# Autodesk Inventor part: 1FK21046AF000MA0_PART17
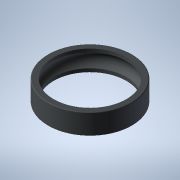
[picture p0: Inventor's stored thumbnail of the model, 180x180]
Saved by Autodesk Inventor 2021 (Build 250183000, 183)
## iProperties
Created: 2025-04
Part Number: 1FK21046AF000MA0_PART17
Material: Generic
Catalog Web Link: www.3dfindit.com
Description: -Servo synchronous motor
Document SubType Name: Modeling
Designer: psAdmin
Mass: 1.64389 g
Surface Area: 26.4305 cm^2
Volume: 1.64389 cm^3
Density: 1 g/cm^3
Appearance: PSOLRGB-212-217-219
Category: PARTsolutions
Title: 1FK21046AF000MA0_PART17
Author: Cadenas PARTsolutions
Comments: Servo synchronous motor
Sending System: PARTsolutions
Preprocessor: ST-DEVELOPER v19.3
PSOL_IDENT_0: {$CADENAS_DATA/23d-libs/siemens_ag/_cat_/1c/1f/1fk21046af000ma0.prj},216 {VTYP=3D},{NB=1FK21046AF000
PSOL_IDENT_1: MA0_PART17},{LINA=1FK21046AF000MA0_PART17},{NN=1FK21046AF000MA0_PART17},{NOPRJ=TRUE},{DATE=19.08.202
PSOL_IDENT_2: 5 14:00:28},{GEOMDATE=30.07.2025 02:02:08},{VERSION=},{LINEID=10},{WBVAR=},{WBNUMERIC=}  {NB=1FK2104
PSOL_IDENT_3: 6AF000MA0_PART17},{LINA=1FK21046AF000MA0_PART17},{KT=DUMMY},{PREVIEW=../../../_pool_/cb/72/p_d211_xx
PSOL_IDENT_4: _00434j.png},{DESCSHORT=SIMOTICS S-1FK2 HD, SINAMICS S210 3AC 400V-480V, 3.2 Nm, 3000 rpm},{DESCLONG=
PSOL_IDENT_5: SIMOTICS S-1FK2 HD servo motor M0=3.2 Nm; PN = 1 kW at nN=3000 rpm (380-480 V); PN = 0.5 kW at nN=15
PSOL_IDENT_6: 00 rpm (200-240 V); degree of protection IP64; cylindrical shaft D19x40mm; absolute encoder 22-bit +
PSOL_IDENT_7: 12-bit multiturn (encoder AM22DQC); with OCC interface; plug size M17, rotatable; SIMOTICS S-1FK2 s
PSOL_IDENT_8: ervomotorfor a wide range of uses in industrial environments. SIMOTICS S‑1FK2 servomotors are compac
PSOL_IDENT_9: t synchronous motors with a high dynamic performance that set themselves apart as a result of their
PSOL_IDENT_10: high power density, degree of protection and overload capability. The motors are available in two va
PSOL_IDENT_11: riants: as High Dynamic variant (highest dynamic performance as a result of the low intrinsic moment
PSOL_IDENT_12: of inertia for applications demanding a high dynamic performance with low moved masses) - and as Co
PSOL_IDENT_13: mpact variant (precise and stable closed-loop control for medium up to large moved masses as a resul
PSOL_IDENT_14: t of a medium intrinsic moment of inertia). SIMOTICSS‑1FK2 servomotors fully exploit their strengths
PSOL_IDENT_15: in a system with the SINAMICSS210 frequency converter and simple connection using the one cable con
PSOL_IDENT_16: nection (OCC). Advantages include the short control and positioning times, fast and precise correcti
PSOL_IDENT_17: on of disturbing quantities as well as stable control with a high dynamic performance. The servo mot
PSOL_IDENT_18: ors can be configured to address a wide range of requirements. For example with and without holding
PSOL_IDENT_19: brake, IP64 or IP65 degree of protection, singleturn or multiturn absolute encoders - to name just a
PSOL_IDENT_20: few. Further, the servomotors are available in different shaft heights extending from 20 to 100. A
PSOL_IDENT_21: shaft sealing ring is available to achieve an IP65 degree of protection and for subsequent mounting
PSOL_IDENT_22: at the motor or as spare part. SIMOTICS - the optimum motor for each and every motion control applic
PSOL_IDENT_23: ation.},{INTNO=195125049666},{SUPPLIERALTNO=1FK2104-6AF00-0MA0},{MANUID=1FK21046AF000MA0},{MANUNAME=
PSOL_IDENT_24: Siemens},{MANUTYPEDESC=Synchronous motor 1FK2-HD 3.2 NM},{AAU732=SIMOTICS},{AAO057=S-1FK2},{AAU734=S
PSOL_IDENT_25: IMOTICS S-1FK2 HD servo motor M0=3.2 Nm; PN = 1 kW at nN=3000 rpm (380-480 V); PN = 0.5 kW at nN=150
PSOL_IDENT_26: 0 rpm (200-240 V); degree of protection IP64; cylindrical shaft D19x40mm; absolute encoder 22-bit +
PSOL_IDENT_27: 12-bit multiturn (encoder AM22DQC); with OCC interface; plug size M17, rotatable;},{AAW338=Synchrono
PSOL_IDENT_28: us motor 1FK2-HD 3.2 NM},{AAO742=SIMOTICS},{AAO663=4042948694374},{NOCUPEROU=1},{PRICEQUANTITY=1},{Q
PSOL_IDENT_29: UANTITYMIN=1},{QUANTITYINT=1},{CTN=85015220},{COO=DE},{AAO676=1FK2104-6AF00-0MA0},{AAO677=Siemens AG
PSOL_IDENT_30: },{ORDERUNIT=C62},{CONTENTUNIT=C62}
NB: 1FK21046AF000MA0_PART17
NT: Servo synchronous motor
NBSYN: $MANUID._PART17
LINA: 1FK21046AF000MA0_PART17
CATALOG: SIEMENS
PREVIEW: ../../../_pool_/cb/72/p_d211_xx_00434j.png
DESCSHORT: SIMOTICS S-1FK2 HD, SINAMICS S210 3AC 400V-480V, 3.2 Nm, 3000 rpm
DESCLONG: SIMOTICS S-1FK2 HD servo motor M0=3.2 Nm; PN = 1 kW at nN=3000 rpm (380-480 V); PN = 0.5 kW at nN=1500 rpm (200-240 V); degree of protection IP64; cylindrical s
INTNO: 195125049666
SUPPLIERALTNO: 1FK2104-6AF00-0MA0
MANUID: 1FK21046AF000MA0
MANUNAME: Siemens
MANUTYPEDESC: Synchronous motor 1FK2-HD 3.2 NM
AAU732: SIMOTICS
AAO057: S-1FK2
AAU734: SIMOTICS S-1FK2 HD servo motor M0=3.2 Nm; PN = 1 kW at nN=3000 rpm (380-480 V); PN = 0.5 kW at nN=1500 rpm (200-240 V); degree of protection IP64; cylindrical s
AAW338: Synchronous motor 1FK2-HD 3.2 NM
AAO742: SIMOTICS
AAO663: 4042948694374.0
NOCUPEROU: 1
PRICEQUANTITY: 1
QUANTITYMIN: 1
QUANTITYINT: 1
CTN: 85015220
COO: DE
ARTICLENO: 1FK21046AF000MA0_PART17
BOMINFO: 1FK21046AF000MA0_PART17
CREATOR: CADENAS GmbH
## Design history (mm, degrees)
feature "2025_04_17_15_39_11_0412"
body "Solid1"
